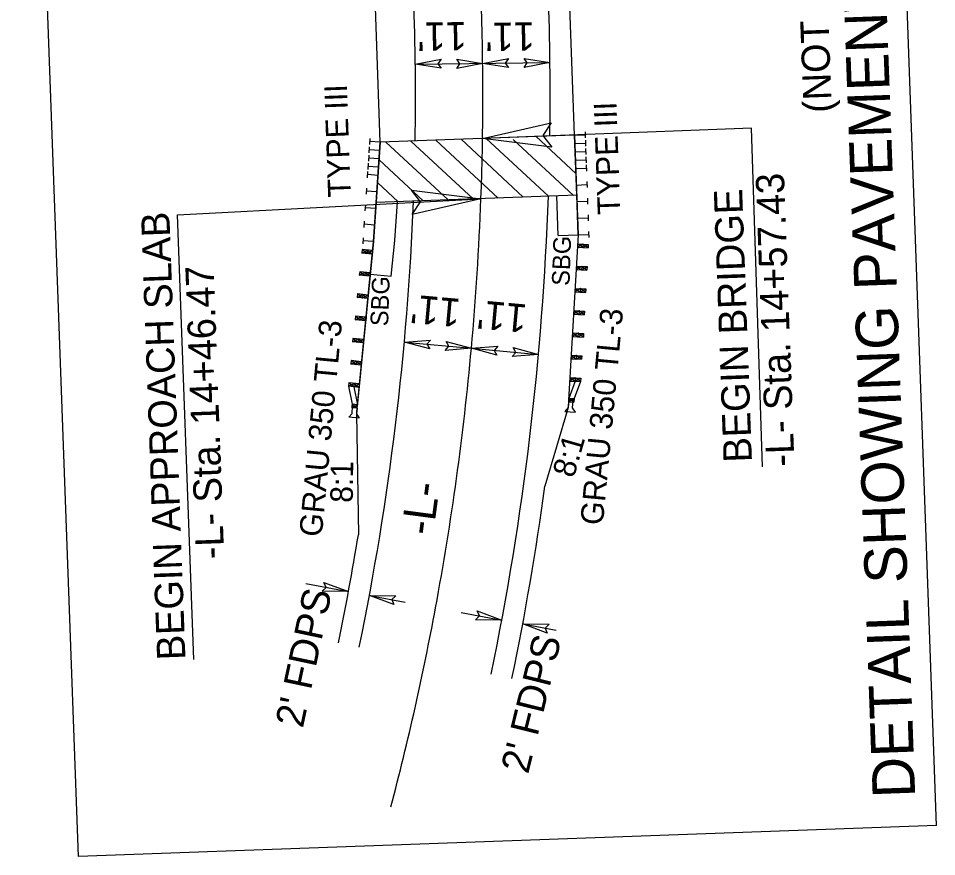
# Model space of a CAD drawing. Extents: x 2065068 to 2066582, y 144283 to 146300.
# Drawn here: x 2065068.5 to 2065327.5, y 145237.3 to 145473.9 of the extents above; entities that cross this region are included whole.
import ezdxf

# ---------------------------------------------------------------- set-up
doc = ezdxf.new("R2010")
doc.units = 0
for name, color, linetype in [('Default', 7, 'Continuous'), ('Prop Approach Slab', 7, 'Continuous'), ('Prop Conc Shoulder Berm Gutter', 7, 'Continuous'), ('Prop Dimension', 7, 'Continuous'), ('Prop Dimension Text', 7, 'Continuous'), ('Prop EOT', 7, 'Continuous'), ('Prop Guardrail Anchor Unit CELL', 7, 'Continuous'), ('Prop Horizontal Alignment', 7, 'Continuous'), ('Prop Horizontal Alignment Station Label', 7, 'Continuous'), ('Prop Paved Shoulder', 7, 'Continuous'), ('Prop Roadway Bridge', 7, 'Continuous'), ('Prop Structure Anchor Unit CELL', 7, 'Continuous'), ('Prop Terminator CELL', 7, 'Continuous')]:
    doc.layers.add(name, color=color, linetype=linetype)

msp = doc.modelspace()

# ---------------------------------------------------------------- linework, layer by layer
at = {"layer": 'Prop Approach Slab'}
for p, q in [((2065210.92, 145423.44), (2065193.36, 145439.78)), ((2065217.99, 145423.69), (2065200.42, 145440.03)), ((2065225.06, 145423.95), (2065208.08, 145439.74)), ((2065225.76, 145430.12), (2065214.56, 145440.55)), ((2065225.99, 145423.98), (2065225.37, 145440.94)), ((2065169.42, 145421.94), (2065170.58, 145438.96)), ((2065189.73, 145422.67), (2065172.16, 145439.01)), ((2065196.79, 145422.93), (2065179.22, 145439.27)), ((2065203.86, 145423.18), (2065186.29, 145439.52)), ((2065182.66, 145422.41), (2065170.24, 145433.97)), ((2065175.59, 145422.16), (2065169.8, 145427.55))]:
    msp.add_line(p, q, dxfattribs=at)
at = {"layer": 'Prop Dimension'}
for p, q in [((2065327.53, 145246.04), (2065310.61, 145714.2)), ((2065085.39, 145237.28), (2065068.47, 145705.45)), ((2065180.45, 145460.98), (2065218.45, 145461.42)), ((2065177.36, 145382.49), (2065196.28, 145380.78)), ((2065196.28, 145380.78), (2065215.21, 145379.07)), ((2065149.56, 145314.35), (2065161.6, 145312.11)), ((2065167.5, 145311.02), (2065177.55, 145309.15)), ((2065193.37, 145306.2), (2065204.86, 145304.07)), ((2065210.75, 145302.97), (2065220.22, 145301.21)), ((2065327.53, 145246.04), (2065085.39, 145237.28))]:
    msp.add_line(p, q, dxfattribs=at)
for points in [[(2065278.38, 145347.28), (2065275.28, 145442.97), (2065199.41, 145440)], [(2065117.94, 145292.92), (2065113.4, 145418.5), (2065198.97, 145423)]]:
    msp.add_lwpolyline(points, dxfattribs=at)
at = {"layer": 'Prop EOT'}
for radius, start, end in [(809, 359.19567, 2.07024), (771, 359.05386, 2.07024), (771, 348.35659, 357.7904), (809, 348.35659, 357.99178)]:
    msp.add_arc((2064409.5, 145452.04), radius, start, end, dxfattribs=at)
at = {"layer": 'Prop Guardrail Anchor Unit CELL'}
for p, q in [((2065226.39, 145412.83), (2065223.7, 145366.16)), ((2065168.66, 145410.9), (2065164.08, 145364.37)), ((2065165.43, 145408.66), (2065165.33, 145407.66)), ((2065165.33, 145407.66), (2065166.92, 145408.51)), ((2065168.41, 145408.37), (2065165.43, 145408.66)), ((2065166.82, 145407.52), (2065165.43, 145408.66)), ((2065166.92, 145408.51), (2065166.82, 145407.52)), ((2065166.92, 145408.51), (2065168.31, 145407.37)), ((2065226.24, 145410.29), (2065226.19, 145409.29)), ((2065227.74, 145410.21), (2065226.19, 145409.29)), ((2065226.19, 145409.29), (2065229.18, 145409.12)), ((2065226.19, 145409.29), (2065227.68, 145409.21)), ((2065226.24, 145410.29), (2065229.24, 145410.12)), ((2065227.68, 145409.21), (2065226.24, 145410.29)), ((2065227.74, 145410.21), (2065227.68, 145409.21)), ((2065227.68, 145409.21), (2065229.24, 145410.12)), ((2065229.18, 145409.12), (2065227.74, 145410.21)), ((2065229.24, 145410.12), (2065229.18, 145409.12)), ((2065168.31, 145407.37), (2065165.33, 145407.66)), ((2065166.82, 145407.52), (2065168.41, 145408.37)), ((2065168.31, 145407.37), (2065166.82, 145407.52)), ((2065168.41, 145408.37), (2065168.31, 145407.37)), ((2065227.41, 145403.91), (2065225.82, 145403)), ((2065225.88, 145404), (2065228.93, 145403.83)), ((2065225.88, 145404), (2065227.35, 145402.91)), ((2065227.41, 145403.91), (2065227.35, 145402.91)), ((2065227.35, 145402.91), (2065228.93, 145403.83)), ((2065228.87, 145402.83), (2065227.41, 145403.91)), ((2065228.93, 145403.83), (2065228.87, 145402.83)), ((2065164.76, 145402.39), (2065164.66, 145401.4)), ((2065164.66, 145401.4), (2065166.28, 145402.24)), ((2065167.7, 145401.1), (2065164.66, 145401.4)), ((2065167.8, 145402.1), (2065164.76, 145402.39)), ((2065166.18, 145401.25), (2065164.76, 145402.39)), ((2065166.28, 145402.24), (2065166.18, 145401.25)), ((2065167.8, 145402.1), (2065166.18, 145401.25)), ((2065166.28, 145402.24), (2065167.7, 145401.1)), ((2065225.82, 145403), (2065228.87, 145402.83)), ((2065164.14, 145396.12), (2065164.05, 145395.13)), ((2065164.05, 145395.13), (2065165.66, 145395.97)), ((2065167.18, 145395.82), (2065164.14, 145396.12)), ((2065165.56, 145394.98), (2065164.14, 145396.12)), ((2065165.66, 145395.97), (2065165.56, 145394.98)), ((2065167.18, 145395.82), (2065165.56, 145394.98)), ((2065165.66, 145395.97), (2065167.08, 145394.83)), ((2065227.04, 145397.62), (2065225.46, 145396.71)), ((2065225.46, 145396.71), (2065228.5, 145396.54)), ((2065225.52, 145397.71), (2065228.56, 145397.54)), ((2065225.52, 145397.71), (2065226.98, 145396.62)), ((2065227.04, 145397.62), (2065226.98, 145396.62)), ((2065226.98, 145396.62), (2065228.56, 145397.54)), ((2065228.5, 145396.54), (2065227.04, 145397.62)), ((2065228.56, 145397.54), (2065228.5, 145396.54)), ((2065167.08, 145394.83), (2065164.05, 145395.13)), ((2065225.16, 145391.42), (2065225.1, 145390.42)), ((2065226.67, 145391.33), (2065225.1, 145390.42)), ((2065225.1, 145390.42), (2065228.13, 145390.25)), ((2065225.16, 145391.42), (2065228.19, 145391.25)), ((2065225.16, 145391.42), (2065226.62, 145390.33)), ((2065226.67, 145391.33), (2065226.62, 145390.33)), ((2065226.62, 145390.33), (2065228.19, 145391.25)), ((2065228.13, 145390.25), (2065226.67, 145391.33)), ((2065228.19, 145391.25), (2065228.13, 145390.25)), ((2065163.54, 145389.85), (2065163.44, 145388.86)), ((2065163.44, 145388.86), (2065165.05, 145389.7)), ((2065166.46, 145388.56), (2065163.44, 145388.86)), ((2065166.56, 145389.55), (2065163.54, 145389.85)), ((2065164.95, 145388.71), (2065163.54, 145389.85)), ((2065165.05, 145389.7), (2065164.95, 145388.71)), ((2065166.56, 145389.55), (2065164.95, 145388.71)), ((2065165.05, 145389.7), (2065166.46, 145388.56)), ((2065166.56, 145389.55), (2065166.46, 145388.56)), ((2065162.82, 145383.59), (2065162.72, 145382.59)), ((2065162.72, 145382.59), (2065164.38, 145383.44)), ((2065165.84, 145382.29), (2065162.72, 145382.59)), ((2065165.94, 145383.28), (2065162.82, 145383.59)), ((2065164.28, 145382.44), (2065162.82, 145383.59)), ((2065164.38, 145383.44), (2065164.28, 145382.44)), ((2065165.94, 145383.28), (2065164.28, 145382.44)), ((2065164.38, 145383.44), (2065165.84, 145382.29)), ((2065226.36, 145385.04), (2065224.74, 145384.13)), ((2065224.74, 145384.13), (2065227.87, 145383.95)), ((2065224.8, 145385.13), (2065227.93, 145384.95)), ((2065224.8, 145385.13), (2065226.3, 145384.04)), ((2065226.36, 145385.04), (2065226.3, 145384.04)), ((2065226.3, 145384.04), (2065227.93, 145384.95)), ((2065227.87, 145383.95), (2065226.36, 145385.04)), ((2065227.93, 145384.95), (2065227.87, 145383.95)), ((2065225.93, 145378.75), (2065224.38, 145377.84)), ((2065224.38, 145377.84), (2065227.37, 145377.67)), ((2065224.43, 145378.84), (2065227.43, 145378.67)), ((2065224.43, 145378.84), (2065225.87, 145377.75)), ((2065225.93, 145378.75), (2065225.87, 145377.75)), ((2065225.87, 145377.75), (2065227.43, 145378.67)), ((2065227.37, 145377.67), (2065225.93, 145378.75)), ((2065227.43, 145378.67), (2065227.37, 145377.67)), ((2065162.34, 145377.31), (2065162.24, 145376.31)), ((2065162.24, 145376.31), (2065163.83, 145377.16)), ((2065165.23, 145376.02), (2065162.24, 145376.31)), ((2065165.32, 145377.01), (2065162.34, 145377.31)), ((2065163.73, 145376.16), (2065162.34, 145377.31)), ((2065163.83, 145377.16), (2065163.73, 145376.16)), ((2065165.32, 145377.01), (2065163.73, 145376.16)), ((2065163.83, 145377.16), (2065165.23, 145376.02)), ((2065225.6, 145372.46), (2065224.01, 145371.55)), ((2065224.07, 145372.55), (2065227.13, 145372.37)), ((2065224.07, 145372.55), (2065225.54, 145371.46)), ((2065225.6, 145372.46), (2065225.54, 145371.46)), ((2065225.54, 145371.46), (2065227.13, 145372.37)), ((2065227.07, 145371.37), (2065225.6, 145372.46)), ((2065227.13, 145372.37), (2065227.07, 145371.37)), ((2065161.66, 145371.04), (2065161.56, 145370.05)), ((2065161.56, 145370.05), (2065163.18, 145370.89)), ((2065164.61, 145369.75), (2065161.56, 145370.05)), ((2065161.56, 145370.05), (2065162.64, 145365.01)), ((2065164.71, 145370.74), (2065161.66, 145371.04)), ((2065163.08, 145369.89), (2065161.66, 145371.04)), ((2065163.18, 145370.89), (2065163.08, 145369.89)), ((2065164.71, 145370.74), (2065163.08, 145369.89)), ((2065163.08, 145369.89), (2065164.13, 145364.87)), ((2065163.18, 145370.89), (2065164.61, 145369.75)), ((2065225.54, 145371.46), (2065223.73, 145366.66)), ((2065224.01, 145371.55), (2065227.07, 145371.37)), ((2065227.07, 145371.37), (2065225.23, 145366.57)), ((2065162.64, 145365.01), (2065162.54, 145364.02)), ((2065162.54, 145364.02), (2065164.13, 145364.87)), ((2065162.64, 145365.01), (2065162.59, 145364.52)), ((2065164.13, 145364.87), (2065162.64, 145365.01)), ((2065164.03, 145363.87), (2065162.64, 145365.01)), ((2065223.78, 145366.12), (2065223.62, 145364.08)), ((2065223.67, 145365.66), (2065225.23, 145366.57)), ((2065223.67, 145365.66), (2065225.17, 145365.57)), ((2065223.73, 145366.66), (2065225.23, 145366.57)), ((2065225.17, 145365.57), (2065223.73, 145366.66)), ((2065224.39, 145366.07), (2065223.78, 145366.12)), ((2065224.99, 145366.03), (2065224.39, 145366.07)), ((2065224.84, 145363.99), (2065224.99, 145366.03)), ((2065225.23, 145366.57), (2065225.17, 145365.57)), ((2065225.23, 145366.57), (2065225.2, 145366.07)), ((2065161.67, 145361.3), (2065162.62, 145362.4)), ((2065164.03, 145363.87), (2065162.54, 145364.02)), ((2065162.62, 145362.4), (2065162.78, 145364.44)), ((2065162.78, 145364.44), (2065163.39, 145364.39)), ((2065163.39, 145364.39), (2065164, 145364.35)), ((2065164, 145364.35), (2065163.84, 145362.3)), ((2065163.84, 145362.3), (2065164.6, 145361.06)), ((2065223.62, 145364.08), (2065222.67, 145362.97)), ((2065222.67, 145362.97), (2065225.61, 145362.75)), ((2065225.61, 145362.75), (2065224.84, 145363.99)), ((2065164.6, 145361.06), (2065161.67, 145361.3))]:
    msp.add_line(p, q, dxfattribs=at)
at = {"layer": 'Prop Horizontal Alignment'}
for start, end in [(357.89352, 2.07024), (354.82455, 357.89352), (349.46053, 354.82455), (345.28271, 349.46053)]:
    msp.add_arc((2064409.5, 145452.04), 790, start, end, dxfattribs=at)
at = {"layer": 'Prop Paved Shoulder'}
for p, q in [((2065168.66, 145410.9), (2065169.42, 145421.94)), ((2065174.65, 145411.2), (2065175.39, 145422.15)), ((2065220.77, 145412.63), (2065220.37, 145423.78)), ((2065226.39, 145412.83), (2065225.99, 145423.98)), ((2065173.65, 145401.1), (2065174.65, 145411.2)), ((2065220.77, 145412.63), (2065226.39, 145412.83)), ((2065226.39, 145412.83), (2065223.7, 145366.16)), ((2065164.03, 145363.87), (2065168.66, 145410.9)), ((2065167.75, 145401.68), (2065173.65, 145401.1)), ((2065223.7, 145366.16), (2065223.62, 145364.08)), ((2065164.03, 145363.87), (2065163.84, 145362.3)), ((2065163.84, 145362.3), (2065164.41, 145328.16)), ((2065223.62, 145364.08), (2065217.02, 145341.84))]:
    msp.add_line(p, q, dxfattribs=at)
for radius, end in [(815, 352.22901), (765, 350.68051)]:
    msp.add_arc((2064409.5, 145452.04), radius, 348.35659, end, dxfattribs=at)
at = {"layer": 'Prop Roadway Bridge'}
for p, q in [((2065225.37, 145440.94), (2065222.48, 145520.87)), ((2065170.58, 145438.96), (2065167.69, 145518.89)), ((2065225.37, 145440.94), (2065170.58, 145438.96)), ((2065225.99, 145423.98), (2065169.42, 145421.94))]:
    msp.add_line(p, q, dxfattribs=at)
at = {"layer": 'Prop Structure Anchor Unit CELL'}
for p, q in [((2065167.64, 145440.02), (2065167.52, 145438.3)), ((2065225.37, 145440.94), (2065228.37, 145441.05)), ((2065225.37, 145440.94), (2065226.39, 145412.83)), ((2065228.34, 145441.9), (2065228.4, 145440.19)), ((2065167.48, 145437.68), (2065167.37, 145435.96)), ((2065170.58, 145438.96), (2065167.58, 145439.16)), ((2065170.58, 145438.96), (2065168.66, 145410.9)), ((2065225.46, 145438.59), (2065228.46, 145438.7)), ((2065228.43, 145439.56), (2065228.49, 145437.84)), ((2065228.51, 145437.22), (2065228.57, 145435.5)), ((2065167.32, 145435.34), (2065167.21, 145433.63)), ((2065170.26, 145434.28), (2065167.26, 145434.48)), ((2065170.42, 145436.62), (2065167.42, 145436.82)), ((2065225.54, 145436.25), (2065228.54, 145436.36)), ((2065228.59, 145434.88), (2065228.66, 145433.16)), ((2065167.16, 145433), (2065167.05, 145431.29)), ((2065170.1, 145431.94), (2065167.1, 145432.15)), ((2065225.63, 145433.91), (2065228.63, 145434.02)), ((2065228.68, 145432.53), (2065228.74, 145430.82)), ((2065167, 145430.66), (2065166.89, 145428.95)), ((2065169.94, 145429.6), (2065166.95, 145429.81)), ((2065225.71, 145431.57), (2065228.71, 145431.68)), ((2065225.88, 145426.88), (2065228.88, 145426.99)), ((2065228.85, 145427.85), (2065228.91, 145426.13)), ((2065166.68, 145425.99), (2065166.57, 145424.27)), ((2065169.62, 145424.93), (2065166.63, 145425.13)), ((2065226.05, 145422.2), (2065229.05, 145422.31)), ((2065229.02, 145423.17), (2065229.08, 145421.45)), ((2065166.37, 145421.31), (2065166.25, 145419.6)), ((2065169.3, 145420.25), (2065166.31, 145420.45)), ((2065166.05, 145416.63), (2065165.93, 145414.92)), ((2065226.22, 145417.51), (2065229.22, 145417.62)), ((2065229.19, 145418.48), (2065229.25, 145416.76)), ((2065168.98, 145415.57), (2065165.99, 145415.78)), ((2065229.36, 145413.8), (2065229.42, 145412.08)), ((2065165.73, 145411.96), (2065165.61, 145410.24)), ((2065168.66, 145410.9), (2065165.67, 145411.1)), ((2065226.39, 145412.83), (2065229.39, 145412.94))]:
    msp.add_line(p, q, dxfattribs=at)
at = {"layer": 'Prop Terminator CELL'}
for points in [[(2065187.76, 145459.82), (2065180.45, 145460.98), (2065187.77, 145462.37), (2065186.85, 145461.07)], [(2065192.14, 145462.36), (2065199.45, 145461.2), (2065192.14, 145459.81), (2065193.05, 145461.12)], [(2065206.76, 145460.04), (2065199.45, 145461.2), (2065206.76, 145462.59), (2065205.85, 145461.29)], [(2065211.15, 145462.61), (2065218.45, 145461.42), (2065211.13, 145460.06), (2065212.05, 145461.36)], [(2065218.99, 145437.6), (2065199.41, 145440), (2065218.77, 145444.4), (2065216.46, 145440.83)], [(2065179.39, 145425.4), (2065198.97, 145423), (2065179.61, 145418.6), (2065181.93, 145422.17)], [(2065184.51, 145380.59), (2065177.36, 145382.49), (2065184.78, 145383.12), (2065183.73, 145381.92)], [(2065189.14, 145382.69), (2065196.28, 145380.78), (2065188.87, 145380.15), (2065189.91, 145381.36)], [(2065203.43, 145378.87), (2065196.28, 145380.78), (2065203.7, 145381.41), (2065202.66, 145380.2)], [(2065208.06, 145380.97), (2065215.21, 145379.07), (2065207.79, 145378.44), (2065208.83, 145379.64)], [(2065154.66, 145314.68), (2065161.6, 145312.11), (2065154.15, 145312.18), (2065155.31, 145313.28)], [(2065174.43, 145308.45), (2065167.5, 145311.02), (2065174.94, 145310.95), (2065173.79, 145309.85)], [(2065197.92, 145306.63), (2065204.86, 145304.07), (2065197.41, 145304.13), (2065198.56, 145305.24)], [(2065217.69, 145300.4), (2065210.75, 145302.97), (2065218.2, 145302.9), (2065217.05, 145301.8)]]:
    msp.add_lwpolyline(points, close=True, dxfattribs=at)

# ---------------------------------------------------------------- texts
at = {"layer": 'Default'}
for rotation, p in [(73.9485, (2065225.15, 145343.96)), (89.304, (2065162.81, 145337.15))]:
    msp.add_text('8:1', height=6.349, rotation=rotation, dxfattribs=at).set_placement(p)
at = {"layer": 'Prop Conc Shoulder Berm Gutter'}
for rotation, p in [(88.0267, (2065223.95, 145398.36)), (88.0227, (2065172.77, 145386.96))]:
    msp.add_text('SBG', height=5, rotation=rotation, dxfattribs=at).set_placement(p)
at = {"layer": 'Prop Dimension'}
for s, height, p in [('DETAIL SHOWING PAVEMENT AND BRIDGE RELATIONSHIP', 12, (2065321.51, 145254.04)), ('(NOT TO SCALE)', 8, (2065297.98, 145447.37)), ('-L- Sta. 14+57.43', 8, (2065287.44, 145347.5)), ('BEGIN BRIDGE', 8, (2065275.44, 145348.68)), ('BEGIN APPROACH SLAB', 8, (2065115.62, 145292.88)), ('-L- Sta. 14+46.47', 8, (2065126.55, 145321.37))]:
    msp.add_text(s, height=height, rotation=92.0702, dxfattribs=at).set_placement(p)
at = {"layer": 'Prop Dimension Text'}
for s, rotation, p in [("11'", 180.7024, (2065194.92, 145472.9)), ("11'", 180.7024, (2065214.1, 145472.84)), ("11'", 174.8245, (2065193.46, 145394.68)), ("11'", 174.8245, (2065212.24, 145393.1)), ("2' FDPS", 78.0107, (2065148.72, 145273.37)), ("2' FDPS", 76.1613, (2065212.27, 145260.39))]:
    msp.add_text(s, height=8, rotation=rotation, dxfattribs=at).set_placement(p)
at = {"layer": 'Prop Guardrail Anchor Unit CELL'}
for p in [(2065233.35, 145330.68), (2065154.05, 145327.38)]:
    msp.add_text('GRAU 350 TL-3', height=6.4, rotation=84.6005, dxfattribs=at).set_placement(p)
at = {"layer": 'Prop Horizontal Alignment Station Label'}
msp.add_text('-L-', height=9.104, rotation=82.4302, dxfattribs=at).set_placement((2065185.46, 145327.73))
at = {"layer": 'Prop Structure Anchor Unit CELL'}
for p in [(2065162.27, 145423.56), (2065238.33, 145418.62)]:
    msp.add_text('TYPE III', height=6.4, rotation=92.0702, dxfattribs=at).set_placement(p)

doc.saveas('drawing.dxf')
